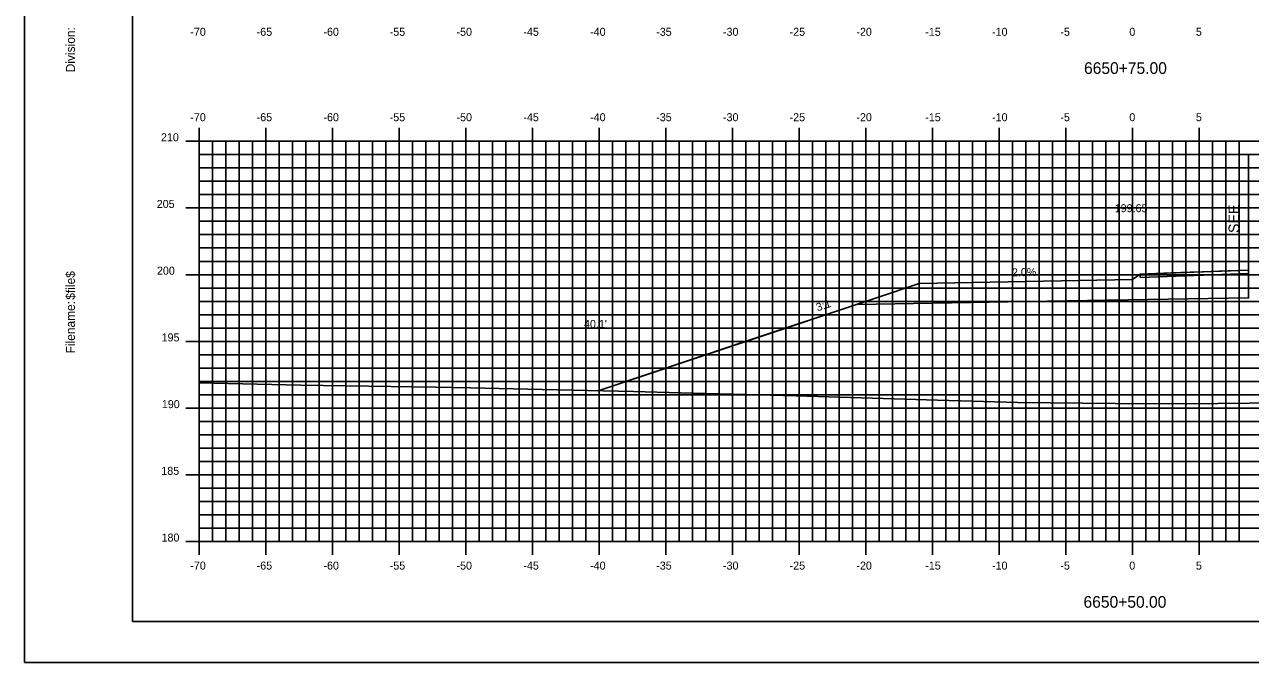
# Model space of a CAD drawing. Extents: x 1723321 to 1723493, y 458501 to 458611.
# Drawn here: x 1723320.9 to 1723412.9, y 458501.2 to 458549 of the extents above; entities that cross this region are included whole.
import ezdxf

# ---------------------------------------------------------------- set-up
doc = ezdxf.new("R2010")
doc.units = 0
for name, color, linetype in [('ANNOTATION', 7, 'Continuous'), ('BORDER', 7, 'Continuous'), ('D_Roadway_Centerline', 7, 'Continuous'), ('D_Roadway_Centerline_Text', 7, 'Continuous'), ('D_Roadway_Drive_Gravel', 7, 'Continuous'), ('D_Roadway_Edge_Shoulder', 7, 'Continuous'), ('D_Roadway_Edge_TW', 7, 'Continuous'), ('D_Roadway_Pavement', 7, 'Continuous'), ('D_Roadway_SlopeLines', 7, 'Continuous'), ('D_Roadway_SubGrade', 7, 'Continuous'), ('D_Text_Standard', 7, 'Continuous'), ('H_V ANNOTATION', 7, 'Continuous'), ('MAJOR', 7, 'Continuous'), ('MINOR', 7, 'Continuous'), ('PLOT BOUNDARY', 7, 'Continuous'), ('S_Roadway_Centerline', 7, 'Continuous')]:
    doc.layers.add(name, color=color, linetype=linetype)

msp = doc.modelspace()

# ---------------------------------------------------------------- linework, layer by layer
msp.add_lwpolyline([(1723363.962, 458521.562), (1723374.458, 458525.061), (1723384.837, 458528.521), (1723388.029, 458529.584), (1723396.029, 458529.744), (1723404.029, 458529.904)])
at = {"layer": 'ANNOTATION'}
for p, q in [((1723404.612, 458530.304), (1723404.029, 458529.904)), ((1723396.124, 458528.238), (1723383.348, 458528.024))]:
    msp.add_line(p, q, dxfattribs=at)
at = {"layer": 'BORDER'}
msp.add_lwpolyline([(1723329.029, 458504.254), (1723489.029, 458504.254), (1723489.029, 458609.254), (1723329.029, 458609.254)], close=True, dxfattribs=at)
at = {"layer": 'D_Roadway_Centerline'}
msp.add_lwpolyline([(1723404.612, 458530.304), (1723406.953, 458530.389), (1723408.348, 458530.44), (1723409.267, 458530.473), (1723410.502, 458530.518), (1723411.197, 458530.544), (1723412.733, 458530.6)], dxfattribs=at)
at = {"layer": 'D_Roadway_Drive_Gravel'}
msp.add_lwpolyline([(1723404.029, 458529.904), (1723396.029, 458529.744), (1723388.029, 458529.584), (1723384.837, 458528.521)], dxfattribs=at)
at = {"layer": 'D_Roadway_Edge_Shoulder'}
msp.add_lwpolyline([(1723412.733, 458530.6), (1723404.612, 458530.304), (1723404.612, 458530.054), (1723412.733, 458530.35)], close=True, dxfattribs=at)
msp.add_lwpolyline([(1723412.733, 458530.6), (1723404.612, 458530.304), (1723404.612, 458530.054), (1723412.733, 458530.35)], close=True, dxfattribs=at)
at = {"layer": 'D_Roadway_Edge_TW'}
msp.add_line((1723412.733, 458530.35), (1723412.733, 458530.6), dxfattribs=at)
msp.add_line((1723412.733, 458530.35), (1723412.733, 458530.6), dxfattribs=at)
msp.add_line((1723412.733, 458530.35), (1723412.733, 458530.6), dxfattribs=at)
at = {"layer": 'D_Roadway_Pavement'}
msp.add_line((1723412.733, 458529.933), (1723412.733, 458530.35), dxfattribs=at)
msp.add_line((1723412.733, 458529.933), (1723412.733, 458530.35), dxfattribs=at)
msp.add_lwpolyline([(1723412.733, 458530.35), (1723412.733, 458529.933)], dxfattribs=at)
at = {"layer": 'D_Roadway_SlopeLines'}
msp.add_lwpolyline([(1723388.029, 458529.584), (1723384.837, 458528.521), (1723363.962, 458521.562)], dxfattribs=at)
at = {"layer": 'D_Roadway_SubGrade'}
for p, q in [((1723412.733, 458539.299), (1723412.733, 458528.516)), ((1723412.733, 458528.516), (1723412.733, 458530.35))]:
    msp.add_line(p, q, dxfattribs=at)
for points in [[(1723404.612, 458530.304), (1723404.612, 458530.054), (1723412.733, 458530.35), (1723412.733, 458528.516), (1723396.124, 458528.238)], [(1723396.124, 458528.238), (1723412.733, 458528.516), (1723412.733, 458529.933), (1723412.733, 458530.35), (1723404.612, 458530.054), (1723404.612, 458530.304)], [(1723404.612, 458530.304), (1723404.612, 458530.054), (1723412.733, 458530.35)], [(1723404.612, 458530.304), (1723404.612, 458530.054), (1723412.733, 458530.35)], [(1723412.733, 458528.516), (1723412.733, 458530.35), (1723412.733, 458529.933)], [(1723412.733, 458528.516), (1723396.124, 458528.238)], [(1723412.733, 458528.516), (1723396.124, 458528.238)]]:
    msp.add_lwpolyline(points, dxfattribs=at)
at = {"layer": 'MAJOR'}
for p, q in [((1723334.029, 458541.256), (1723334.029, 458540.254)), ((1723339.029, 458541.256), (1723339.029, 458540.254)), ((1723344.029, 458541.256), (1723344.029, 458540.254)), ((1723349.029, 458541.256), (1723349.029, 458540.254)), ((1723354.029, 458541.256), (1723354.029, 458540.254)), ((1723359.029, 458541.256), (1723359.029, 458540.254)), ((1723364.029, 458541.256), (1723364.029, 458540.254)), ((1723369.029, 458541.256), (1723369.029, 458540.254)), ((1723374.029, 458541.256), (1723374.029, 458540.254)), ((1723379.029, 458541.256), (1723379.029, 458540.254)), ((1723384.029, 458541.256), (1723384.029, 458540.254)), ((1723389.029, 458541.256), (1723389.029, 458540.254)), ((1723394.029, 458541.256), (1723394.029, 458540.254)), ((1723399.029, 458541.256), (1723399.029, 458540.254)), ((1723404.029, 458541.256), (1723404.029, 458540.254)), ((1723409.029, 458541.256), (1723409.029, 458540.254)), ((1723333.027, 458540.254), (1723334.029, 458540.254)), ((1723334.029, 458540.254), (1723474.029, 458540.254)), ((1723334.029, 458510.254), (1723334.029, 458540.254)), ((1723334.029, 458510.254), (1723334.029, 458540.254)), ((1723334.029, 458540.254), (1723474.029, 458540.254)), ((1723339.029, 458510.254), (1723339.029, 458540.254)), ((1723344.029, 458510.254), (1723344.029, 458540.254)), ((1723349.029, 458510.254), (1723349.029, 458540.254)), ((1723354.029, 458510.254), (1723354.029, 458540.254)), ((1723359.029, 458510.254), (1723359.029, 458540.254)), ((1723364.029, 458510.254), (1723364.029, 458540.254)), ((1723369.029, 458510.254), (1723369.029, 458540.254)), ((1723374.029, 458510.254), (1723374.029, 458540.254)), ((1723379.029, 458510.254), (1723379.029, 458540.254)), ((1723384.029, 458510.254), (1723384.029, 458540.254)), ((1723389.029, 458510.254), (1723389.029, 458540.254)), ((1723394.029, 458510.254), (1723394.029, 458540.254)), ((1723399.029, 458510.254), (1723399.029, 458540.254)), ((1723404.029, 458510.254), (1723404.029, 458540.254)), ((1723409.029, 458510.254), (1723409.029, 458540.254)), ((1723333.027, 458535.254), (1723334.029, 458535.254)), ((1723334.029, 458535.254), (1723474.029, 458535.254)), ((1723333.027, 458530.254), (1723334.029, 458530.254)), ((1723334.029, 458530.254), (1723474.029, 458530.254)), ((1723333.027, 458525.254), (1723334.029, 458525.254)), ((1723334.029, 458525.254), (1723474.029, 458525.254)), ((1723333.027, 458520.254), (1723334.029, 458520.254)), ((1723334.029, 458520.254), (1723474.029, 458520.254)), ((1723333.027, 458515.254), (1723334.029, 458515.254)), ((1723334.029, 458515.254), (1723474.029, 458515.254)), ((1723333.027, 458510.254), (1723334.029, 458510.254)), ((1723334.029, 458510.254), (1723474.029, 458510.254)), ((1723334.029, 458510.254), (1723474.029, 458510.254)), ((1723334.029, 458509.252), (1723334.029, 458510.254)), ((1723339.029, 458509.252), (1723339.029, 458510.254)), ((1723344.029, 458509.252), (1723344.029, 458510.254)), ((1723349.029, 458509.252), (1723349.029, 458510.254)), ((1723354.029, 458509.252), (1723354.029, 458510.254)), ((1723359.029, 458509.252), (1723359.029, 458510.254)), ((1723364.029, 458509.252), (1723364.029, 458510.254)), ((1723369.029, 458509.252), (1723369.029, 458510.254)), ((1723374.029, 458509.252), (1723374.029, 458510.254)), ((1723379.029, 458509.252), (1723379.029, 458510.254)), ((1723384.029, 458509.252), (1723384.029, 458510.254)), ((1723389.029, 458509.252), (1723389.029, 458510.254)), ((1723394.029, 458509.252), (1723394.029, 458510.254)), ((1723399.029, 458509.252), (1723399.029, 458510.254)), ((1723404.029, 458509.252), (1723404.029, 458510.254)), ((1723409.029, 458509.252), (1723409.029, 458510.254))]:
    msp.add_line(p, q, dxfattribs=at)
at = {"layer": 'MINOR'}
for p, q in [((1723335.029, 458510.254), (1723335.029, 458540.254)), ((1723336.029, 458510.254), (1723336.029, 458540.254)), ((1723337.029, 458510.254), (1723337.029, 458540.254)), ((1723338.029, 458510.254), (1723338.029, 458540.254)), ((1723340.029, 458510.254), (1723340.029, 458540.254)), ((1723341.029, 458510.254), (1723341.029, 458540.254)), ((1723342.029, 458510.254), (1723342.029, 458540.254)), ((1723343.029, 458510.254), (1723343.029, 458540.254)), ((1723345.029, 458510.254), (1723345.029, 458540.254)), ((1723346.029, 458510.254), (1723346.029, 458540.254)), ((1723347.029, 458510.254), (1723347.029, 458540.254)), ((1723348.029, 458510.254), (1723348.029, 458540.254)), ((1723350.029, 458510.254), (1723350.029, 458540.254)), ((1723351.029, 458510.254), (1723351.029, 458540.254)), ((1723352.029, 458510.254), (1723352.029, 458540.254)), ((1723353.029, 458510.254), (1723353.029, 458540.254)), ((1723355.029, 458510.254), (1723355.029, 458540.254)), ((1723356.029, 458510.254), (1723356.029, 458540.254)), ((1723357.029, 458510.254), (1723357.029, 458540.254)), ((1723358.029, 458510.254), (1723358.029, 458540.254)), ((1723360.029, 458510.254), (1723360.029, 458540.254)), ((1723361.029, 458510.254), (1723361.029, 458540.254)), ((1723362.029, 458510.254), (1723362.029, 458540.254)), ((1723363.029, 458510.254), (1723363.029, 458540.254)), ((1723365.029, 458510.254), (1723365.029, 458540.254)), ((1723366.029, 458510.254), (1723366.029, 458540.254)), ((1723367.029, 458510.254), (1723367.029, 458540.254)), ((1723368.029, 458510.254), (1723368.029, 458540.254)), ((1723370.029, 458510.254), (1723370.029, 458540.254)), ((1723371.029, 458510.254), (1723371.029, 458540.254)), ((1723372.029, 458510.254), (1723372.029, 458540.254)), ((1723373.029, 458510.254), (1723373.029, 458540.254)), ((1723375.029, 458510.254), (1723375.029, 458540.254)), ((1723376.029, 458510.254), (1723376.029, 458540.254)), ((1723377.029, 458510.254), (1723377.029, 458540.254)), ((1723378.029, 458510.254), (1723378.029, 458540.254)), ((1723380.029, 458510.254), (1723380.029, 458540.254)), ((1723381.029, 458510.254), (1723381.029, 458540.254)), ((1723382.029, 458510.254), (1723382.029, 458540.254)), ((1723383.029, 458510.254), (1723383.029, 458540.254)), ((1723385.029, 458510.254), (1723385.029, 458540.254)), ((1723386.029, 458510.254), (1723386.029, 458540.254)), ((1723387.029, 458510.254), (1723387.029, 458540.254)), ((1723388.029, 458510.254), (1723388.029, 458540.254)), ((1723390.029, 458510.254), (1723390.029, 458540.254)), ((1723391.029, 458510.254), (1723391.029, 458540.254)), ((1723392.029, 458510.254), (1723392.029, 458540.254)), ((1723393.029, 458510.254), (1723393.029, 458540.254)), ((1723395.029, 458510.254), (1723395.029, 458540.254)), ((1723396.029, 458510.254), (1723396.029, 458540.254)), ((1723397.029, 458510.254), (1723397.029, 458540.254)), ((1723398.029, 458510.254), (1723398.029, 458540.254)), ((1723400.029, 458510.254), (1723400.029, 458540.254)), ((1723401.029, 458510.254), (1723401.029, 458540.254)), ((1723402.029, 458510.254), (1723402.029, 458540.254)), ((1723403.029, 458510.254), (1723403.029, 458540.254)), ((1723405.029, 458510.254), (1723405.029, 458540.254)), ((1723406.029, 458510.254), (1723406.029, 458540.254)), ((1723407.029, 458510.254), (1723407.029, 458540.254)), ((1723408.029, 458510.254), (1723408.029, 458540.254)), ((1723410.029, 458510.254), (1723410.029, 458540.254)), ((1723411.029, 458510.254), (1723411.029, 458540.254)), ((1723412.029, 458510.254), (1723412.029, 458540.254)), ((1723334.029, 458539.254), (1723474.029, 458539.254)), ((1723334.029, 458539.254), (1723335.031, 458539.254)), ((1723334.029, 458538.254), (1723474.029, 458538.254)), ((1723334.029, 458538.254), (1723335.031, 458538.254)), ((1723334.029, 458537.254), (1723474.029, 458537.254)), ((1723334.029, 458537.254), (1723335.031, 458537.254)), ((1723334.029, 458536.254), (1723474.029, 458536.254)), ((1723334.029, 458536.254), (1723335.031, 458536.254)), ((1723334.029, 458534.254), (1723474.029, 458534.254)), ((1723334.029, 458534.254), (1723335.031, 458534.254)), ((1723334.029, 458533.254), (1723474.029, 458533.254)), ((1723334.029, 458533.254), (1723335.031, 458533.254)), ((1723334.029, 458532.254), (1723474.029, 458532.254)), ((1723334.029, 458532.254), (1723335.031, 458532.254)), ((1723334.029, 458531.254), (1723474.029, 458531.254)), ((1723334.029, 458531.254), (1723335.031, 458531.254)), ((1723334.029, 458529.254), (1723474.029, 458529.254)), ((1723334.029, 458529.254), (1723335.031, 458529.254)), ((1723334.029, 458528.254), (1723335.031, 458528.254)), ((1723334.029, 458528.254), (1723474.029, 458528.254)), ((1723397.093, 458528.254), (1723474.029, 458528.254)), ((1723334.029, 458527.254), (1723474.029, 458527.254)), ((1723334.029, 458527.254), (1723335.031, 458527.254)), ((1723334.029, 458526.254), (1723474.029, 458526.254)), ((1723334.029, 458526.254), (1723335.031, 458526.254)), ((1723334.029, 458524.254), (1723474.029, 458524.254)), ((1723334.029, 458524.254), (1723335.031, 458524.254)), ((1723334.029, 458523.254), (1723474.029, 458523.254)), ((1723334.029, 458523.254), (1723335.031, 458523.254)), ((1723334.029, 458522.254), (1723474.029, 458522.254)), ((1723334.029, 458522.254), (1723335.031, 458522.254)), ((1723334.029, 458521.254), (1723474.029, 458521.254)), ((1723334.029, 458521.254), (1723335.031, 458521.254)), ((1723334.029, 458519.254), (1723474.029, 458519.254)), ((1723334.029, 458519.254), (1723335.031, 458519.254)), ((1723334.029, 458518.254), (1723474.029, 458518.254)), ((1723334.029, 458518.254), (1723335.031, 458518.254)), ((1723334.029, 458517.254), (1723474.029, 458517.254)), ((1723334.029, 458517.254), (1723335.031, 458517.254)), ((1723334.029, 458516.254), (1723474.029, 458516.254)), ((1723334.029, 458516.254), (1723335.031, 458516.254)), ((1723334.029, 458514.254), (1723474.029, 458514.254)), ((1723334.029, 458514.254), (1723335.031, 458514.254)), ((1723334.029, 458513.254), (1723474.029, 458513.254)), ((1723334.029, 458513.254), (1723335.031, 458513.254)), ((1723334.029, 458512.254), (1723474.029, 458512.254)), ((1723334.029, 458512.254), (1723335.031, 458512.254)), ((1723334.029, 458511.254), (1723474.029, 458511.254)), ((1723334.029, 458511.254), (1723335.031, 458511.254))]:
    msp.add_line(p, q, dxfattribs=at)
at = {"layer": 'PLOT BOUNDARY'}
msp.add_lwpolyline([(1723320.936, 458501.195), (1723490.936, 458501.195), (1723490.936, 458611.195), (1723320.936, 458611.195)], close=True, dxfattribs=at)
at = {"layer": 'S_Roadway_Centerline'}
msp.add_lwpolyline([(1723334.029, 458522.142), (1723341.667, 458521.983), (1723351.773, 458521.819), (1723354.382, 458521.764), (1723359.747, 458521.655), (1723366.618, 458521.503), (1723370.12, 458521.41), (1723378.797, 458521.182), (1723389.414, 458520.85), (1723395.439, 458520.688), (1723402.733, 458520.609), (1723408.098, 458520.587), (1723415.095, 458520.651), (1723426.488, 458519.88), (1723426.746, 458519.86), (1723427.174, 458519.88), (1723438.85, 458520.337), (1723447.205, 458519.694), (1723461.333, 458519.284), (1723464.581, 458519.256), (1723470.841, 458519.067), (1723474.029, 458518.951)], dxfattribs=at)

# ---------------------------------------------------------------- texts
at = {"layer": 'ANNOTATION'}
for s, height, rotation, p in [('SEE', 0.8, 90, (1723412.03, 458533.373)), ('2.0%', 0.6, 1.14576, (1723394.992, 458530.124)), ('3:1', 0.6, 18.43495, (1723380.413, 458527.5))]:
    msp.add_text(s, height=height, rotation=rotation, dxfattribs=at).set_placement(p)
at = {"layer": 'BORDER'}
for s, p in [('Division:', (1723324.714, 458545.42)), ('$file$', (1723324.714, 458528.38)), ('Filename:', (1723324.714, 458524.353))]:
    msp.add_text(s, height=0.6696, rotation=90, dxfattribs=at).set_placement(p)
at = {"layer": 'D_Roadway_Centerline_Text'}
msp.add_text('199.65', height=0.6, dxfattribs=at).set_placement((1723402.694, 458534.936))
at = {"layer": 'D_Text_Standard'}
msp.add_text("40.1'", height=0.6, dxfattribs=at).set_placement((1723362.895, 458526.262))
at = {"layer": 'H_V ANNOTATION'}
for s, height, p in [('-70', 0.6, (1723333.37, 458548.154)), ('-65', 0.6, (1723338.346, 458548.154)), ('-60', 0.6, (1723343.354, 458548.154)), ('-55', 0.6, (1723348.325, 458548.154)), ('-50', 0.6, (1723353.333, 458548.154)), ('-45', 0.6, (1723358.346, 458548.154)), ('-40', 0.6, (1723363.354, 458548.154)), ('-35', 0.6, (1723368.309, 458548.154)), ('-30', 0.6, (1723373.317, 458548.154)), ('-25', 0.6, (1723378.314, 458548.154)), ('-20', 0.6, (1723383.322, 458548.154)), ('-15', 0.6, (1723388.486, 458548.154)), ('-10', 0.6, (1723393.494, 458548.154)), ('-5', 0.6, (1723398.619, 458548.154)), ('0', 0.6, (1723403.788, 458548.154)), ('5', 0.6, (1723408.78, 458548.154)), ('6650+75.00', 0.875, (1723400.392, 458545.297)), ('-70', 0.6, (1723333.37, 458541.754)), ('-65', 0.6, (1723338.346, 458541.754)), ('-60', 0.6, (1723343.354, 458541.754)), ('-55', 0.6, (1723348.325, 458541.754)), ('-50', 0.6, (1723353.333, 458541.754)), ('-45', 0.6, (1723358.346, 458541.754)), ('-40', 0.6, (1723363.354, 458541.754)), ('-35', 0.6, (1723368.309, 458541.754)), ('-30', 0.6, (1723373.317, 458541.754)), ('-25', 0.6, (1723378.314, 458541.754)), ('-20', 0.6, (1723383.322, 458541.754)), ('-15', 0.6, (1723388.486, 458541.754)), ('-10', 0.6, (1723393.494, 458541.754)), ('-5', 0.6, (1723398.619, 458541.754)), ('0', 0.6, (1723403.788, 458541.754)), ('5', 0.6, (1723408.78, 458541.754)), ('210', 0.6, (1723331.169, 458540.254)), ('205', 0.6, (1723330.853, 458535.254)), ('200', 0.6, (1723330.869, 458530.254)), ('195', 0.6, (1723331.218, 458525.254)), ('190', 0.6, (1723331.234, 458520.254)), ('185', 0.6, (1723331.196, 458515.254)), ('180', 0.6, (1723331.212, 458510.254)), ('-70', 0.6, (1723333.37, 458508.154)), ('-65', 0.6, (1723338.346, 458508.154)), ('-60', 0.6, (1723343.354, 458508.154)), ('-55', 0.6, (1723348.325, 458508.154)), ('-50', 0.6, (1723353.333, 458508.154)), ('-45', 0.6, (1723358.346, 458508.154)), ('-40', 0.6, (1723363.354, 458508.154)), ('-35', 0.6, (1723368.309, 458508.154)), ('-30', 0.6, (1723373.317, 458508.154)), ('-25', 0.6, (1723378.314, 458508.154)), ('-20', 0.6, (1723383.322, 458508.154)), ('-15', 0.6, (1723388.486, 458508.154)), ('-10', 0.6, (1723393.494, 458508.154)), ('-5', 0.6, (1723398.619, 458508.154)), ('0', 0.6, (1723403.788, 458508.154)), ('5', 0.6, (1723408.78, 458508.154)), ('6650+50.00', 0.875, (1723400.353, 458505.297))]:
    msp.add_text(s, height=height, dxfattribs=at).set_placement(p)
at = {"layer": 'MAJOR'}
msp.add_text('-', height=0.006, dxfattribs=at).set_placement((1723334.024, 458510.254))

doc.saveas('drawing.dxf')
